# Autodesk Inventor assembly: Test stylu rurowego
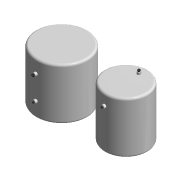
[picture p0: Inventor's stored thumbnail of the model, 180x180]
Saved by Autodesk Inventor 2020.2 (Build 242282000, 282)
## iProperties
Created: 2014-09
Part Number: Test stylu rurowego
Document SubType Name: Assembly
Designer: F.Stasiak
Catalog Web Link: www.expertbooks.pl
Manager: www.cadconsulting.pl
Company: Fabian Stasiak CAD Consulting
Author: F.Stasiak
Subject: Zbiór ćwiczeń. Autodesk Inventor 2020. Kurs Professional
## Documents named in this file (5)
- C:\2020_Kurs_Professional\R1 Rury\Test stylu rurowego.iam
- C:\2020_Kurs_Professional\R1 Rury\Konstrukcja_11.ipt
- C:\2020_Kurs_Professional\Zasoby\ContentCenter\pl-PL\ASME B16.11(21)\ASME B16.11 Półzłączka nakrętna z gwintem - klasa 6000 1_2 x 1_2.ipt
- C:\2020_Kurs_Professional\Zasoby\ContentCenter\pl-PL\ASME B16.11(21)\ASME B16.11 Półzłączka nakrętna z gwintem - klasa 6000 1 x 1.ipt
- C:\2020_Kurs_Professional\R1 Rury\Test stylu rurowego\AIP\Przewody rurowe\Test stylu rurowego.Przebiegi przewodów rurowych.iam
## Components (6 placed, 4 different names)
1. Konstrukcja_11:1 — Wstaw:1, Wstaw:2, Wstaw:3, Wstaw:4
2. ASME B16.11 Półzłączka nakrętna z gwintem - klasa 6000 1/2 x 1/2:1 — Wstaw:1
3. ASME B16.11 Półzłączka nakrętna z gwintem - klasa 6000 1/2 x 1/2:2 — Wstaw:2
4. ASME B16.11 Półzłączka nakrętna z gwintem - klasa 6000 1 x 1:1 — Wstaw:4
5. ASME B16.11 Półzłączka nakrętna z gwintem - klasa 6000 1 x 1:2 — Wstaw:3
6. Przebiegi przewodów rurowych 00 [sub-assembly]
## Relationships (4: Insert 4)
- Wstaw:1 [Insert]: Konstrukcja_11:1 ↔ ASME B16.11 Półzłączka nakrętna z gwintem - klasa 6000 1/2 x 1/2:1
- Wstaw:2 [Insert]: Konstrukcja_11:1 ↔ ASME B16.11 Półzłączka nakrętna z gwintem - klasa 6000 1/2 x 1/2:2
- Wstaw:3 [Insert]: Konstrukcja_11:1 ↔ ASME B16.11 Półzłączka nakrętna z gwintem - klasa 6000 1 x 1:2
- Wstaw:4 [Insert]: Konstrukcja_11:1 ↔ ASME B16.11 Półzłączka nakrętna z gwintem - klasa 6000 1 x 1:1
